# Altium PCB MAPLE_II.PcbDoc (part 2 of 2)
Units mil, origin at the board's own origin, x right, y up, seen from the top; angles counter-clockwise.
Board outline 3200 x 2150 mil, 6 copper layers (Top Side, Ground Plane, MidLayer1, MidLayer2, Power Plane, Bottom Side), stack 49.2 mil thick; 130 components, 162 nets, 713 pads, 399 vias.
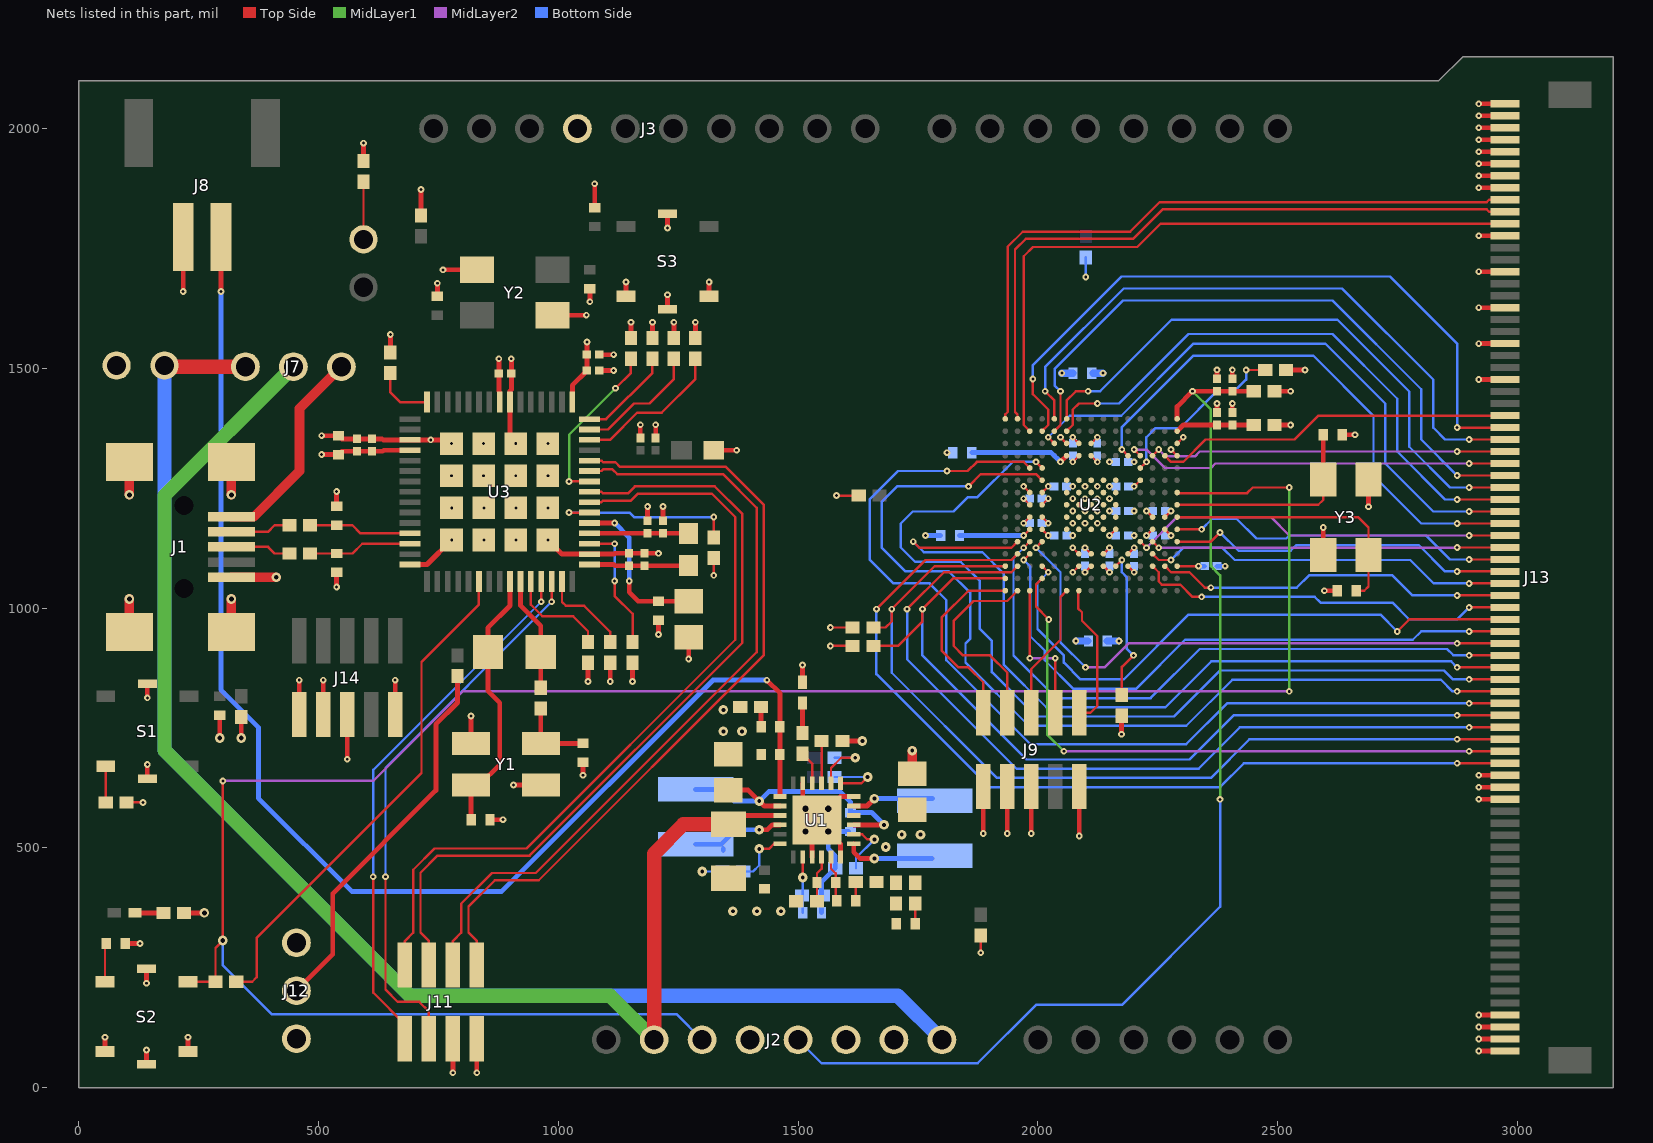
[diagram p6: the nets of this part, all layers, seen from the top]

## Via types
v1: diameter 14, hole 6, Top Side to Bottom Side, 362 vias
v2: diameter 20, hole 8, Top Side to Bottom Side, 23 vias
v3: diameter 20, hole 10, Top Side to Bottom Side, 10 vias
v4: diameter 25.98, hole 12.99, Top Side to Bottom Side, tented top, 4 vias

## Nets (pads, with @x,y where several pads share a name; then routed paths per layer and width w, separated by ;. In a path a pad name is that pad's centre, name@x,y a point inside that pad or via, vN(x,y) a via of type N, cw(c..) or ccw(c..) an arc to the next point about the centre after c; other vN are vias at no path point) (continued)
GND: C1.1 C2.1 C3.1 C4.1 C5.1 C6.1 C7.1 C8.1 C10.1 C14.1 C15.1 C16.1 C17.1 C18.1 C19.1 C20.1 C21.1 C22.1 C23.1 C24.1 C25.1 C26.1 C27.1 C28.1 C29.1 C30.1 C31.1 C32.1 C33.1 C34.1 C35.1 C36.1 C37.1 C38.1 C39.1 C40.1 C41.1 C43.1 C44.1 C47.1 C48.1 C49.1 C50.1 C51.1 C52.1 C53.1 C54.1 C55.1 C56.1 C57.1 C58.1 C59.1 C60.1 C61.1 C62.1 C63.1 J1.5 J1.S J2.2 J2.3 J3.7 J6.1 J8.2 J9.3 J9.5 J9.9 J11.4 J12.3 J13.1 J13.2 J13.3 J13.4 J13.11 J13.16 J13.17 J13.22 J13.23 J13.57 J13.58 J13.60 J13.78 J13.80 J14.3 J14.5 J14.9 R2.2 R4.2 R5.2 R6.2 R10.2 R12.1 R18.2 R20.2 R24.2 R33.2 R39.2 S1.5 S1.6 S2.3 S2.4 S2.5 S2.6 S3.3 S3.4 S3.5 S3.6 U1.3 U1.6 U1.12 U1.17 U1.25 U2.D5 U2.D7 U2.D8 U2.D9 U2.F2 U2.F6 U2.F7 U2.F8 U2.F9 U2.F10 U2.F12 U2.G2 U2.G6 U2.G7 U2.G8 U2.G9 U2.G10 U2.G12 U2.H6 U2.H7 U2.H8 U2.H9 U2.H10 U2.H12 U2.J6 U2.J7 U2.J8 U2.J9 U2.J10 U2.K6 U2.K7 U2.K8 U2.K9 U2.K10 U2.M1 U2.M8 U2.M9 U2.N1 U3.7 U3.18 U3.30 U3.47 U3.PAD1 U3.PAD2 U3.PAD3 U3.PAD4 U3.PAD5 U3.PAD6 U3.PAD7 U3.PAD8 U3.PAD9 U3.PAD10 U3.PAD11 U3.PAD12 U3.PAD13 U3.PAD14 U3.PAD15 U3.PAD16 Y1.2 Y1.4 Y2.2 Y2.4 Y3.2 Y3.4 | length 5115.7
  Top Side w5: R2.2@100,594.98 v1(134.35,594.98) ; U2.F12@2008.86,1164.37 v1(2021.65,1151.57) ; U2.G12@2008.86,1189.96 v1(2021.65,1177.17) ; U2.H12@2008.86,1215.55 v1(2021.65,1228.35) ; v1(2072.83,1125.98) U2.D9@2085.63,1113.19 ; v1(2072.83,1305.12) U2.M9@2085.63,1317.91 ; v1(2098.43,1125.98) U2.D8@2111.22,1113.19 ; U2.M8@2111.22,1317.91 v1(2124.02,1305.12) ; U2.D7@2136.81,1113.19 v1(2149.61,1125.98) ; v1(2149.61,1151.57) U2.F6@2162.4,1164.37 ; U2.D5@2187.99,1113.19 v1(2200.79,1125.98) ; U2.F2@2264.76,1164.37 v1(2277.56,1151.57) ; U2.G2@2264.76,1189.96 v1(2277.56,1202.76) ; v1(2277.56,1330.71) U2.M1@2290.35,1317.91 ; U2.N1@2290.35,1343.5 v1(2303.15,1356.3)
  Top Side w10: S2.3@55,75.49 v1(55,105.37) ; C41.1@96.95,300.69 v1(127.95,300.69) ; S2.6@141.61,48.92 v1(141.61,78.8) ; v1(141.61,217.86) S2.5@141.61,247.74 ; S1.6@143.31,644 v1(143.31,673.87) ; v1(143.31,812.94) S1.5@143.31,842.81 ; v1(218,1660.32) J8.2@218,1774 ; S2.4@228.23,75.49 v1(228.23,105.37) ; v3(294.29,729.33) C1.1@294.29,776.87 ; v1(506.69,1359.69) C52.1@542,1359.69 548.69,1352.99 C53.1@612,1352.99 633.01,1352.99 ; J14.3@510,778.23 v1(510,850) ; v1(538,1044) C40.1@538,1074.63 ; C39.1@538,1212.69 v1(538,1243.31) ; v1(560,685) J14.5@560,778.23 ; R20.2@594,1932.31 v1(594,1969.65) ; 635.11,1350.89 U3.18@690.94,1350.89 U3.PAD13@769.69,1350.89 ; R24.2@650,1533.31 v1(650,1570.62) ; J14.9@660,778.23 v1(660,850) ; U3.30@690.94,1091.04 726.38,1091.04 U3.PAD16@777.56,1142.22 ; C61.1@748,1650.3 v1(748,1677.36) ; v1(759.72,1705.41) Y2.2@830.42,1705.41 ; v1(780.31,31.32) J11.4@780.31,102.36 ; Y1.4@818.33,718 v1(818.33,775.17) ; C5.1@857.7,559 v1(884.77,559) ; U3.PAD5@899.61,1354.82 U3.7@899.61,1429.63 899.61,1452.61 902.26,1455.26 v1@902.26,1520 ; v1(906.83,631.39) Y1.2@964,631.39 ; U3.PAD4@978.35,1142.22 1007.87,1112.7 U3.47@1064.96,1112.7 1116.3,1112.7 1117.99,1114.39 C50.1@1147.53,1114.39 C51.1@1179.52,1114.39 v1(1209,1114.39) ; Y2.4@987.9,1610.93 v1(1058.6,1610.93) ; v1(1051.52,651.56) C4.1@1051.52,678.63 ; v1(1066,1638.98) C60.1@1066,1666.04 ; C59.1@1076,1835.11 v1(1076,1885) ; C49.1@1085.46,1495.53 v1(1115.47,1495.53) ; C48.1@1085.46,1528.53 v1(1115.47,1528.53) ; S3.3@1141.41,1650.07 v1(1141.41,1679.95) ; R33.2@1151.57,1563.48 v1(1151.57,1596.18) ; v1(1155,847) R39.2@1155,886.35 ; C58.1@1171.19,1354.98 v1(1171.19,1382.44) ; C55.1@1186.39,1181.98 v1(1186.39,1211.99) ; C57.1@1203.18,1354.98 v1(1203.18,1382.44) ; v1(1209,945) C44.1@1209,975.03 ; C56.1@1218.39,1181.99 v1(1218.37,1211.99) ; S3.6@1228.02,1623.5 v1(1228.02,1653.37) ; v1(1228.02,1792.44) S3.5@1228.02,1822.31 ; v1(1272,894) C43.1@1272,939.6 ; S3.4@1314.64,1650.07 v1(1314.64,1679.95) ; U1.25@1509.72,587.52 U1.17@1509.72,634.76 ; U1.3@1529.41,481.22 U1.25@1529.41,548.15 ; U1.25@1539.25,557.99 1588.46,508.78 U1.6@1588.46,481.22 ; U1.25@1588.46,607.2 U1.12@1616.02,607.2 ; R5.2@1592.56,722.99 v2(1634.25,722.99) ; v1(1936.29,530) J9.3@1936.29,628.3 ; v1(1986.29,530) J9.5@1986.29,628.3 ; v1(2086.29,525) J9.9@2086.29,628.3 ; C15.1@2373.52,1407.87 v1(2373.52,1426.67) ; C30.1@2373.52,1478.05 v1(2373.52,1496.85) ; C16.1@2405.51,1407.87 v1(2405.51,1426.67) ; C29.1@2405.51,1478.05 v1(2405.51,1496.85) ; R18.2@2517.56,1496.58 v1(2556.91,1496.58) ; Y3.4@2594.98,1111.22 v1(2594.98,1168.39) ; v1(2597.44,1036.42) C62.1@2624.51,1036.42 ; C63.1@2634.35,1361.58 v1(2661.42,1361.58) ; v1(2689.47,1211.53) Y3.2@2689.47,1268.7 ; v1(2919.25,101.58) J13.80@2974.25,101.58 ; v1(2919.25,151.58) J13.78@2974.25,151.58 ; v1(2919.25,601.58) J13.60@2974.25,601.58 ; v1(2919.25,626.58) J13.57@2974.25,626.58 ; v1(2919.25,651.58) J13.58@2974.25,651.58 ; v1(2919.25,1476.58) J13.23@2974.25,1476.58 ; v1(2919.25,1551.58) J13.22@2974.25,1551.58 ; v1(2919.25,1626.58) J13.17@2974.25,1626.58 ; v1(2919.25,1701.58) J13.16@2974.25,1701.58 ; v1(2919.25,1776.58) J13.11@2974.25,1776.58 ; v1(2919.25,1976.58) J13.3@2974.25,1976.58 ; v1(2919.25,2001.58) J13.4@2974.25,2001.58 ; v1(2919.25,2026.58) J13.1@2974.25,2026.58 ; v1(2919.25,2051.58) J13.2@2974.25,2051.58
  Top Side w20: J1.S@105.91,950.49 v3(105.91,1019.19) ; v3(105.91,1236.12) J1.S@105.91,1304.82 ; J1.S@318.5,950.49 v3(318.5,1019.19) ; J1.5@318.5,1064.67 v3(412.11,1064.67) ; v3(318.5,1236.12) J1.S@318.5,1304.82 ; C10.1@1738.25,654.39 v2(1738.25,702.99)
  Bottom Side w10: C6.1@1548.62,364.99 1548.62,429.01 R12.1@1577.6,457.99 1577.6,483.64 1562.87,498.37 v4(1562.87,534.37) C7.1@1605.31,534.37 ; v1(1765.75,1151.57) C17.1@1797.24,1151.57 ; C28.1@2373.72,1087.6 v1(2390.6,1087.6)
  Bottom Side w15: v1(2079.25,931.58) C19.1@2104.57,931.58 ; C31.1@2114.68,1490 v1(2136,1490)
  other v1: 778,1142 844.93,1142 911.86,1142 978.79,1142 2072.83,1177.17 2098.43,1177.17 2124.02,1177.17 2072.83,1202.76 2098.43,1202.76 2124.02,1202.76 2149.61,1202.76 778,1209 844.93,1209 911.86,1209 978.79,1209 2072.83,1228.35 2098.43,1228.35 2124.02,1228.35 2149.61,1228.35 2072.83,1253.94 2098.43,1253.94 2124.02,1253.94 2149.61,1253.94 777.56,1276.08 844.49,1276.08 911.42,1276.08 978.35,1276.08 2149.61,1305.12 1810.53,1324.31 777.56,1343.01 844.49,1343.01 911.42,1343.01 978.35,1343.01 734.25,1350.89 902,1520
  other v2: 1364.25,367.99 1414.25,367.99 1464.25,367.99 1344.25,742.99 1383.25,742.99 1344.25,787.99
  other v4: 1515.63,534.37 1515.63,581.61 1562.87,581.61
HD0: J13.28 U2.M2 | length 754.7
  Top Side w5: U2.M2@2264.76,1317.91 2277.56,1305.12 2303.15,1305.12 2349.61,1351.58 2535.14,1351.58 2585.14,1401.58 J13.28@2974.25,1401.58
HD1: J13.29 U2.M3 | length 750.4
  Top Side w5: U2.M3@2239.17,1317.91 v1(2251.97,1330.71) ; v1(2874.25,1326.58) J13.29@2974.25,1326.58
  MidLayer2 w5: v1(2251.97,1330.71) 2266.1,1316.58 2327.41,1316.58 2337.41,1326.58 v1(2874.25,1326.58)
HD2: J13.32 U2.M4 | length 811.3
  Top Side w5: v1(2200.79,1330.71) U2.M4@2213.58,1317.91 ; v1(2899.25,1301.58) J13.32@2974.25,1301.58
  MidLayer2 w5: v1(2200.79,1330.71) 2226.38,1330.71 2264.76,1292.32 2360.73,1292.32 2369.98,1301.58 v1(2899.25,1301.58)
HD3: J13.35 U2.M5 | length 1143.9
  Top Side w5: v1(2175.2,1330.71) U2.M5@2187.99,1317.91 ; v1(2874.25,1176.58) J13.35@2974.25,1176.58
  Bottom Side w5: v1(2175.2,1330.71) 2175.2,1377.52 2324.25,1526.58 2574.25,1526.58 2699.8,1401.03 2699.8,1276.03 2799.25,1176.58 v1(2874.25,1176.58)
HD4: J13.39 U2.E1 | length 735.5
  Top Side w5: U2.E1@2290.35,1138.78 2360.73,1138.78 v1(2379.92,1157.97) ; v1(2874.25,1076.58) J13.39@2974.25,1076.58
  Bottom Side w5: v1(2379.92,1157.97) 2418.31,1119.59 2527.26,1119.59 2539.25,1131.58 2794.25,1131.58 2849.25,1076.58 v1(2874.25,1076.58)
HD5: J13.40 U2.F1 | length 733.6
  Top Side w5: U2.F1@2290.35,1164.37 v1(2341.54,1164.37) ; v1(2899.25,1101.58) J13.40@2974.25,1101.58
  Bottom Side w5: v1(2341.54,1164.37) 2363.74,1186.58 2414.25,1186.58 2455.65,1145.18 2517.85,1145.18 2524.25,1151.58 2809.25,1151.58 2859.25,1101.58 v1(2899.25,1101.58)
HD6: J13.27 U2.P12 | length 1450.5
  Top Side w5: v1(1989.67,1477.85) 1989.67,1445.87 2021.65,1413.88 2021.65,1381.89 U2.P12@2008.86,1369.09 ; v1(2874.25,1376.58) J13.27@2974.25,1376.58
  Bottom Side w5: v1(1989.67,1477.85) 1989.67,1506.99 2174.25,1691.58 2734.25,1691.58 2874.25,1551.58 v1(2874.25,1376.58)
HD7: J13.53 R28.2 U2.C15 | length 1878.7
  Top Side w5: R28.2@1656.99,959.65 1682.58,959.65 1695.37,972.44 v1(1695.37,998.03) 1784.94,1087.6 U2.C15@1932.09,1087.6 ; v1(2874.25,726.58) J13.53@2974.25,726.58
  Bottom Side w5: v1(1695.37,998.03) 1695.37,865.46 1914.67,646.16 2360.73,646.16 2441.15,726.58 v1(2874.25,726.58)
HD8: J13.51 R31.2 U2.B15 | length 1787.8
  Top Side w5: R31.2@1656.99,921.26 1708.17,921.26 1759.35,972.44 v1(1759.35,998.03) 1823.33,1062.01 U2.B15@1932.09,1062.01 ; v1(2874.25,776.58) J13.51@2974.25,776.58
  Bottom Side w5: v1(1759.35,998.03) 1759.35,901.48 1976.28,684.55 2315.94,684.55 2407.98,776.58 v1(2874.25,776.58)
HD9: J13.56 U2.B12 | length 1312.8
  Top Side w5: U2.B12@2008.86,1062.01 1996.06,1049.21 1996.06,1003.31 v1(2022.79,976.58) ; v1(2899.25,701.58) J13.56@2974.25,701.58
  MidLayer2 w5: v1(2054.25,701.58) v1(2899.25,701.58)
  MidLayer1 w5: v1(2022.79,976.58) 2019.25,973.04 2019.25,736.58 v1(2054.25,701.58)
HD10: J13.43 U2.C12 | length 1253.6
  Top Side w5: U2.C12@2008.86,1087.6 v1(2021.65,1074.8) ; v1(2749.25,951.58) 2774.25,976.58 J13.43@2974.25,976.58
  Bottom Side w5: v1(2021.65,1074.8) 1999.25,1052.4 1999.25,956.58 2054.25,901.58 2054.25,886.58 2089.25,851.58 2179.25,851.58 2314.25,986.58 2714.25,986.58 v1(2749.25,951.58)
HD11: J13.33 U2.P10 | length 1224.2
  Top Side w5: U2.P10@2060.04,1369.09 2072.83,1381.89 2072.83,1413.88 2085.63,1426.67 v1(2124.02,1426.67) ; v1(2874.25,1226.58) J13.33@2974.25,1226.58
  Bottom Side w5: v1(2124.02,1426.67) 2169.35,1426.67 2314.25,1571.58 2614.25,1571.58 2749.25,1436.58 2749.25,1326.58 2849.25,1226.58 v1(2874.25,1226.58)
HD12: J13.34 U2.R10 | length 1234.7
  Top Side w5: U2.R10@2060.04,1394.69 2060.04,1433.07 2079.23,1452.26 v1(2104.82,1452.26) ; v1(2899.25,1251.58) J13.34@2974.25,1251.58
  Bottom Side w5: v1(2104.82,1452.26) 2129.94,1452.26 2279.25,1601.58 2624.25,1601.58 2774.25,1451.58 2774.25,1336.58 2859.25,1251.58 v1(2899.25,1251.58)
HD13: J13.36 U2.N11 | length 1269.8
  Top Side w5: v1(2021.65,1356.3) U2.N11@2034.45,1343.5 ; v1(2899.25,1201.58) J13.36@2974.25,1201.58
  Bottom Side w5: v1(2021.65,1356.3) 2066.44,1401.08 2173.76,1401.08 2324.25,1551.58 2599.25,1551.58 2724.25,1426.58 2724.25,1301.58 2824.25,1201.58 v1(2899.25,1201.58)
HD14: J13.31 U2.P11 | length 1351.3
  Top Side w5: U2.P11@2034.45,1369.09 2047.24,1381.89 v1(2047.24,1452.26) ; v1(2874.25,1276.58) J13.31@2974.25,1276.58
  Bottom Side w5: v1(2047.24,1452.26) 2035,1464.51 2035,1499 2177.58,1641.58 2614.25,1641.58 2799.25,1456.58 2799.25,1351.58 v1(2874.25,1276.58)
HD15: J13.30 U2.R11 | length 1331.8
  Top Side w5: v1(2015.26,1452.26) 2034.45,1433.07 U2.R11@2034.45,1394.69 ; v1(2899.25,1351.58) J13.30@2974.25,1351.58
  Bottom Side w5: v1(2015.26,1452.26) 2015.26,1502.58 2179.25,1666.58 2634.25,1666.58 2824.25,1476.58 2824.25,1376.58 2849.25,1351.58 v1(2899.25,1351.58)
HD16: J13.52 U2.L13 | length 2089.8
  Top Side w5: v1(1810.53,1285.93) 1853.6,1285.93 1872.79,1305.12 1970.47,1305.12 U2.L13@1983.27,1292.32 ; v1(2899.25,801.58) J13.52@2974.25,801.58
  Bottom Side w5: v1(1810.53,1285.93) 1708.6,1285.93 1649.25,1226.58 1649.25,1101.58 1699.25,1051.58 1774.25,1051.58 1809.25,1016.58 1809.25,891.58 1984.3,716.54 2309.55,716.54 2394.59,801.58 v1(2899.25,801.58)
HD17: J13.50 U2.L12 | length 1953.2
  Top Side w5: v1(1996.06,1305.12) U2.L12@2008.86,1292.32 ; v1(2899.25,851.58) J13.50@2974.25,851.58
  Bottom Side w5: v1(1996.06,1305.12) 1947.79,1305.12 1874.25,1231.58 1854.25,1231.58 1824.25,1201.58 1739.25,1201.58 1714.25,1176.58 1714.25,1126.58 1744.25,1096.58 1839.25,1096.58 1879.25,1056.58 1879.25,956.58 1904.25,931.58 1904.25,866.58 1996.72,774.11 2283.96,774.11 2379.92,870.08 2846.95,870.08 2865.45,851.58 v1(2899.25,851.58)
HD18: J13.49 U2.K12 | length 2061.8
  Top Side w5: v1(1855.32,1253.94) 1880.91,1279.53 1996.06,1279.53 U2.K12@2008.86,1266.73 ; v1(2874.25,826.58) J13.49@2974.25,826.58
  Bottom Side w5: v1(1855.32,1253.94) 1706.61,1253.94 1674.25,1221.58 1674.25,1126.58 1724.25,1076.58 1814.25,1076.58 1859.25,1031.58 1859.25,936.58 1849.25,926.58 1849.25,886.58 1980.91,754.92 2309.55,754.92 2405.51,850.89 2840.55,850.89 2864.86,826.58 v1(2874.25,826.58)
HD19: J13.45 U2.E12 | length 1206.2
  Top Side w5: v1(1996.06,1125.98) U2.E12@2008.86,1138.78 ; v1(2874.25,926.58) J13.45@2974.25,926.58
  MidLayer2 w5: v1(2099.25,876.58) 2139.25,876.58 2189.25,926.58 v1(2874.25,926.58)
  Bottom Side w5: v1(1996.06,1125.98) 2047.24,1074.8 2047.24,928.59 2098.79,877.04 v1@2098.79,876.11
HD20: J13.48 U2.E13 | length 1361.1
  Top Side w5: v1(1970.47,1125.98) U2.E13@1983.27,1138.78 ; v1(2899.25,901.58) J13.48@2974.25,901.58
  Bottom Side w5: v1(1970.47,1125.98) 1949.25,1104.76 1949.25,901.58 2038.33,812.5 2235.17,812.5 2337.54,914.86 2853.35,914.86 2866.14,902.07 2898.76,902.07 v1(2899.25,901.58)
HD21: J13.46 U2.D13 | length 1279.5
  Top Side w5: v1(1970.47,1100.39) U2.D13@1983.27,1113.19 ; v1(2899.25,951.58) J13.46@2974.25,951.58
  Bottom Side w5: v1(1970.47,1100.39) 1984.25,1086.61 1984.25,941.58 2014.25,911.58 2014.25,891.58 2074.14,831.69 2204.37,831.69 2306.73,934.06 2781.73,934.06 2799.25,951.58 v1(2899.25,951.58)
HD22: J13.44 U2.C3 | length 802.7
  Top Side w5: U2.C3@2239.17,1087.6 2251.97,1074.8 2251.97,1055.61 2258.37,1049.21 2296.75,1049.21 2322.34,1023.62 v1(2341.54,1023.62) ; v1(2899.25,1001.58) J13.44@2974.25,1001.58
  Bottom Side w5: v1(2341.54,1023.62) 2577.21,1023.62 2589.25,1011.58 2739.25,1011.58 2774.25,976.58 2874.25,976.58 v1(2899.25,1001.58)
HD23: J13.41 U2.C2 | length 755.8
  Top Side w5: U2.C2@2264.76,1087.6 2277.56,1074.8 2316.03,1074.8 2348.02,1042.81 v1(2360.73,1042.81) ; v1(2874.25,1026.58) J13.41@2974.25,1026.58
  Bottom Side w5: v1@2360.98,1042.56 2539.61,1042.56 2565.45,1068.41 2739.25,1068.41 2781.08,1026.58 v1(2874.25,1026.58)
HD24: J13.47 U2.E14 | length 1761.6
  Top Side w5: v1(1740.16,1138.78) 1752.95,1125.98 1944.88,1125.98 U2.E14@1957.68,1138.78 ; v1(2874.25,876.58) J13.47@2974.25,876.58
  Bottom Side w5: v1(1740.16,1138.78) 1762.36,1116.58 1884.25,1116.58 1929.25,1071.58 1929.25,881.58 2017.52,793.31 2265.98,793.31 2361.94,889.27 2861.56,889.27 v1(2874.25,876.58)
HD25: J13.55 U2.D14 | length 1906.5
  Top Side w5: v1(1663.39,998.03) 1765.75,1100.39 1944.88,1100.39 U2.D14@1957.68,1113.19 ; v1(2874.25,676.58) J13.55@2974.25,676.58
  Bottom Side w5: v1(1663.39,998.03) 1663.39,862.44 1898.86,626.97 2379.92,626.97 2429.53,676.58 v1(2874.25,676.58)
HD26: J13.54 U2.C14 | length 1749.1
  Top Side w5: v1(1727.36,998.03) 1804.13,1074.8 1944.88,1074.8 U2.C14@1957.68,1087.6 ; v1(2899.25,751.58) J13.54@2974.25,751.58
  Bottom Side w5: v1(1727.36,998.03) 1727.36,893.47 1955.48,665.35 2335.14,665.35 2421.36,751.58 v1(2899.25,751.58)
HD27: J13.42 U2.D3 | length 782.3
  Top Side w5: U2.D3@2239.17,1113.19 2251.97,1100.39 v1(2277.56,1100.39) ; v1(2899.25,1051.58) J13.42@2974.25,1051.58
  Bottom Side w5: v1(2277.56,1100.39) 2303.74,1126.58 2384.25,1126.58 2410.44,1100.39 2776.57,1100.39 2825.39,1051.58 v1(2899.25,1051.58)
HD28: J13.37 U2.E3 | length 740.4
  Top Side w5: U2.E3@2239.17,1138.78 v1(2251.97,1125.98) ; v1(2874.25,1126.58) J13.37@2974.25,1126.58
  MidLayer2 w5: v1(2251.97,1125.98) v1@2874.25,1125.98
HD29: J13.38 U2.E4 | length 808.4
  Top Side w5: U2.E4@2213.58,1138.78 v1(2226.38,1125.98) ; v1(2899.25,1151.58) J13.38@2974.25,1151.58
  MidLayer2 w5: v1(2226.38,1125.98) 2290.35,1189.96 2485.87,1189.96 2524.25,1151.58 v1(2899.25,1151.58)
JTAG_TCK: J9.4 U2.A14 | length 430.5
  Top Side w5: J9.4@1936.29,781.84 1936.29,865.87 1900.59,901.58 1844.25,901.58 1824.25,921.58 1824.25,973.37 1865.92,1015.03 1936.29,1015.03 U2.A14@1957.68,1036.42
JTAG_TDI: J9.8 U2.A13 | length 307.6
  Top Side w5: v1(1983.27,895.67) U2.A13@1983.27,1036.42 ; J9.8@2036.29,781.84 v1(2036.29,895.67)
  MidLayer2 w5: v1(1983.27,895.67) v1(2036.29,895.67)
JTAG_TDO: J9.6 U2.A10 | length 285.1
  Top Side w5: J9.6@1986.29,781.84 1986.29,873.1 2047.24,934.06 2047.24,1023.62 U2.A10@2060.04,1036.42
JTAG_TMS: J9.2 U2.A15 | length 402.9
  Top Side w5: J9.2@1886.29,781.84 1886.29,845.5 1855.21,876.58 1834.25,876.58 1799.25,911.58 1799.25,980.35 1855.31,1036.42 U2.A15@1932.09,1036.42
JTAG_TRST: J9.10 U2.A9 | length 301.9
  Top Side w5: J9.10@2085.63,781.84 2109.52,781.84 2124.25,796.58 2124.25,941.58 2092.03,973.8 2092.03,991.63 2084,999.66 2084,1034.79 U2.A9@2085.63,1036.42
LINK_LED: J11.6 U3.43 | length 1160.5
  Top Side w5: v1(639.76,440) 639.76,204.72 665.35,179.13 710.14,179.13 730.31,158.96 J11.6@730.31,102.36 ; v1(986.22,1013.29) U3.43@986.22,1055.61
  Bottom Side w5: v1(639.76,440) 639.76,666.83 v1(986.22,1013.29)
M\C\U\_\R\S\T\: J2.6 R22.1 S2.1 U2.J1 | length 4562.7
  Top Side w5: S2.1@228.23,221.16 R22.1@285.35,221.16 285.35,291.74 v3(300.69,307.09) v1(300.69,639.76) ; U2.J1@2290.35,1241.14 2291.5,1240 2436.36,1240 2447.94,1251.58 v1(2524.25,1251.58)
  MidLayer2 w5: v1(300.69,639.76) 614.17,639.76 800.99,826.58 v1(2524.25,826.58)
  MidLayer1 w5: v1(2524.25,826.58) v1(2524.25,1251.58)
  Bottom Side w5: v3(300.69,307.09) 300.69,255.14 402.29,153.54 1246.46,153.54 J2.6@1300,100
NetC4_2: C4.2 R25.2 Y1.3 | length 159.9
  Top Side w10: Y1.3@963.58,718.42 R25.2@963.58,790.85 ; Y1.3@964,718 C4.2@1051.52,718
NetC5_2: C5.2 R21.1 U3.39 Y1.1 | length 543.6
  Top Side w10: C5.2@818.33,559 Y1.1@818.33,631.39 ; Y1.1@835.39,631.39 878,674 878,803 853.35,827.65 R21.1@853.35,908.46 853.35,959.35 899.61,1005.61 U3.39@899.61,1055.61
NetC6_2: C6.2 R4.1 U1.2 | length 116.2
  Top Side w5: v2(1509.72,438.46) U1.2@1509.72,481.22
  Bottom Side w5: C6.2@1509.72,364.99 v2(1509.72,438.46)
NetC8_2: C8.2 C9.2 J8.1 U1.19 | length 2779.8
  Top Side w10: v1(296.74,1660.32) J8.1@296.74,1774 ; v1(1435,850) 1462.48,822.52 U1.19@1462.48,607.2
  Bottom Side w10: v1(296.74,1660.32) 296.74,830 375,751.74 375,603.84 569.39,409.45 882.12,409.45 1322.67,850 v1(1435,850)
NetC9_1: C9.1 R6.1 | length 41
  Top Side w10: C9.1@1422.88,752.99 R6.1@1422.91,793.99
NetC11_1: C11.1 C13.1 R7.2 R9.2 R10.1 U1.4 | length 96.2
  Top Side w5: R10.1@1539.57,388.99 1539.57,447.3 1549.09,456.83 U1.4@1549.09,481.22
NetC11_2: C11.2 R8.2 | length 42
  Top Side w5: C11.2@1744.25,342.3 R8.2@1744.25,384.33
NetC12_1: C12.1 R9.1 | length 38.7
  Top Side w5: C12.1@1619.94,389.99 R9.1@1619.94,428.67
NetC12_2: C12.2 C13.2 U1.5 | length 95.2
  Top Side w5: U1.5@1568.78,481.22 1568.78,456.83 1578.31,447.3 C12.2@1578.31,389.99
NetC15_2: C15.2 C16.2 R16.2 U2.P1 | length 165.2
  Top Side w10: U2.P1@2290.35,1369.09 2303.15,1381.89 C15.2@2373.52,1381.89 C16.2@2405.51,1381.89 R16.2@2450.3,1381.89
NetC17_2: C17.2 U2.F13 | length 152
  Top Side w5: v1(1970.47,1151.57) U2.F13@1983.27,1164.37
  Bottom Side w10: C17.2@1836.61,1151.57 v1(1970.47,1151.57)
NetC18_2: C18.2 U2.M10 | length 211.1
  Top Side w10: v1(2047.24,1305.12) U2.M10@2060.04,1317.91
  Bottom Side w10: C18.2@1862.2,1324.31 2028.05,1324.31 v1(2047.24,1305.12)
NetC41_2: C41.2 S2.2 | length 76.9
  Top Side w5: S2.2@55,221.16 C41.2@55,298.11
NetC43_2: C43.2 C44.2 U3.50 | length 341.6
  Top Side w10: U3.50@1064.96,1177.66 v1(1117.65,1177.66) ; v1(1148,1056.65) 1148,1033 1166.6,1014.4 C44.2@1209,1014.4 C43.2@1272,1014.4
  Bottom Side w10: v1(1117.65,1177.66) 1148,1147.31 v1(1148,1056.65)
NetJ10_2: J10.2 R20.1 | length 120
  Top Side w5: J10.2@594,1769 R20.1@594,1889
NetJ12_2: J12.2 R43.1 | length 795.1
  Top Side w10: J12.2@454.23,202.36 530,278.13 530,405 745,620 745,758 790,803 R43.1@790,858.35
NetL1_1: L1.1 U1.22 | length 196.9
  Top Side w10: v2(1419.25,537.99) 1436.25,537.99 1446.41,548.15 U1.22@1462.48,548.15
  Bottom Side w10: L1.1@1286.25,507.9 1340.17,507.9 1370.25,537.99 v2(1419.25,537.99) ; L1.1@1344.17,494.9 L1.1@1344.17,498.9
NetL2_1: L2.1 U1.7 | length 186.4
  Top Side w10: U1.7@1616.02,508.78 1616.02,491.22 1629.25,477.99 v2(1659.25,477.99)
  Bottom Side w10: v2(1659.25,477.99) L2.1@1779.34,477.99
NetL2_2: L2.2 U1.11 | length 170.7
  Top Side w10: U1.11@1616.02,587.52 1643.78,587.52 v2(1659.25,602.99)
  Bottom Side w10: v2(1659.25,602.99) L2.2@1780.34,602.99
NetLED1_1: LED1.1 R3.2 | length 59.1
  Top Side w10: LED1.1@117.62,364.67 R3.2@176.67,364.67
NetLED2_2: LED2.2 R11.1 | length 62.7
  Top Side w10: R11.1@1509.25,739.64 LED2.2@1509.25,802.33
NetR2_1: R2.1 S1.3 | length 75.6
  Top Side w5: R2.1@56.69,594.98 S1.3@56.69,670.57
NetR5_1: R5.1 U1.15 | length 88.1
  Top Side w5: U1.15@1549.09,634.76 R5.1@1549.09,722.83
NetR11_2: R11.2 U1.16 | length 69.9
  Top Side w5: R11.2@1509.25,696.33 1529.41,676.18 U1.16@1529.41,634.76
NetR12_2: R12.2 U1.8 | length 123.4
  Top Side w5: U1.8@1616.02,528.46 1633.78,528.46 1644.25,517.99 v2(1659.25,517.99)
  Bottom Side w5: R12.2@1620.91,457.99 1620.91,479.64 v2(1659.25,517.99)
NetR13_2: R13.2 U1.13 | length 130.8
  Top Side w5: U1.13@1588.46,634.76 1631.76,634.76 v2(1645,648)
  Bottom Side w5: R13.2@1576.25,647.99 v2(1645,648)
NetR14_2: R14.2 U1.14 | length 134.1
  Top Side w5: U1.14@1568.78,634.76 1568.78,666.52 1590.25,687.99 v2(1619.25,687.99)
  Bottom Side w5: R14.2@1576.25,687.99 v2(1619.25,687.99)
NetR17_1: R17.1 U2.C6 | length 319.5
  Top Side w5: U2.C6@2162.4,1087.6 v1(2175.2,1100.39) ; R17.1@2175.2,818.9 2175.2,877.52 v1(2199.25,901.58)
  Bottom Side w5: v1(2175.2,1100.39) 2175.2,1074.8 2185,1065 2185,915.83 v1(2199.25,901.58)
NetR18_1: R18.1 U2.L4 | length 387
  Top Side w5: U2.L4@2213.58,1292.32 v1(2226.38,1305.12) ; v1(2434.25,1496.58) R18.1@2474.25,1496.58
  Bottom Side w5: v1(2226.38,1305.12) 2226.38,1356.3 2245.57,1375.49 2296.75,1375.49 2372.84,1451.58 2409.25,1451.58 2434.25,1476.58 v1(2434.25,1496.58)
NetR21_2: R21.2 R25.1 U3.40 | length 239
  Top Side w10: U3.40@921.26,1055.61 921.26,1005.74 963.58,963.42 R25.1@963.58,834.15
NetR22_2: R22.2 U3.36 | length 1063.5
  Top Side w5: R22.2@328.65,221.16 361.91,221.16 371.06,230.31 371.06,312.06 715,656 715,888 834.65,1007.65 U3.36@834.65,1055.61
NetR23_1: R23.1 U1.24 | length 120.4
  Top Side w5: v2(1419.25,497.99) 1439.25,497.99 1450.04,508.78 U1.24@1462.48,508.78
  Bottom Side w5: R23.1@1385.91,450.99 1406.25,450.99 1419.25,463.99 v2(1419.25,497.99)
NetR24_1: R24.1 U3.15 | length 124.8
  Top Side w5: R24.1@650,1490 650,1450 670.37,1429.63 U3.15@726.38,1429.63
NetR29_1: R29.1 U3.44 | length 189.9
  Top Side w5: U3.44@1007.87,1055.61 1007.87,1013.13 1016,1005 1054,1005 1108.5,950.5 R29.1@1108.5,929.65
NetR30_1: R30.1 U3.58 | length 315.9
  Top Side w5: U3.58@1064.96,1350.89 1107.78,1350.89 1164.37,1407.48 1215.55,1407.48 1285.93,1477.85 R30.1@1285.93,1520.18
NetR32_1: R32.1 U3.51 | length 390.2
  Top Side w5: v1(1022.64,1199.31) U3.51@1064.96,1199.31 ; R32.1@1324.31,1147.64 v1(1324.31,1189.96)
  Bottom Side w5: v1(1022.64,1199.31) 1148.62,1199.31 1157.97,1189.96 v1(1324.31,1189.96)
NetR33_1: R33.1 U3.54 | length 351.6
  Top Side w5: v1(1022.64,1264.27) U3.54@1064.96,1264.27 ; v1(1119.59,1458.66) 1151.57,1490.65 R33.1@1151.57,1520.18
  MidLayer1 w5: v1(1022.64,1264.27) 1022.64,1361.71 v1(1119.59,1458.66)
NetR39_1: R39.1 U3.48 | length 272.4
  Top Side w5: U3.48@1064.96,1134.35 v1(1117.65,1134.35) ; v1(1117.65,1056.65) 1117.65,1025.56 1155,988.21 R39.1@1155,930.12
  Bottom Side w5: v1(1117.65,1056.65) v1(1117.65,1134.35)
NetR40_2: R40.2 U3.41 | length 212.8
  Top Side w5: U3.41@942.91,1055.61 942.91,1007.09 967,983 1031,983 1062.01,951.99 R40.2@1062.01,929.65
NetR41_2: R41.2 U3.60 | length 200.9
  Top Side w5: U3.60@1064.96,1394.19 1099.9,1394.19 1196.36,1490.65 R41.2@1196.36,1520.18
NetR42_2: R42.2 U3.59 | length 262.1
  Top Side w5: U3.59@1064.96,1372.54 1103.84,1372.54 1157.97,1426.67 1189.96,1426.67 1241.14,1477.85 R42.2@1241.14,1520.18
RXI_N: J11.1 U3.56 | length 1677.7
  Top Side w5: J11.1@830.31,255.91 830.31,306 812.81,323.5 812.81,377.78 867.87,432.83 959.46,432.83 1428.88,902.25 1428.88,1215.37 1349.72,1294.53 1129.13,1294.53 1119.4,1304.25 1093.33,1304.25 1090,1307.58 U3.56@1064.96,1307.58
RXI_P: J11.3 U3.55 | length 1652.8
  Top Side w5: J11.3@780.31,255.91 780.31,306 797.81,323.5 797.81,383.99 861.66,447.83 953.25,447.83 1413.88,908.46 1413.88,1209.15 1343.5,1279.53 1122.91,1279.53 1113.19,1289.25 1093.33,1289.25 1090,1285.93 U3.55@1064.96,1285.93
SPEED_LED: J11.8 U3.42 | length 1125.8
  Top Side w5: v1(614.17,440) 614.17,198.33 680.31,132.19 J11.8@680.31,102.36 ; v1(964.57,1013.29) U3.42@964.57,1055.61
  Bottom Side w5: v1(614.17,440) 614.17,662.89 v1(964.57,1013.29)
TXO_N: J11.5 U3.53 | length 1688.4
  Top Side w5: J11.5@730.31,255.91 730.31,306 712.81,323.5 712.81,448.31 748.52,484.02 940.27,484.02 1384.09,927.84 1384.09,1196.17 1326.33,1253.94 1159.82,1253.94 1145.18,1239.29 1093.33,1239.29 1090,1242.62 U3.53@1064.96,1242.62
TXO_P: J11.7 U3.52 | length 1663.5
  Top Side w5: J11.7@680.31,255.91 680.31,306 697.81,323.5 697.81,454.52 742.31,499.02 934.06,499.02 1369.09,934.06 1369.09,1189.96 1320.12,1238.94 1166.04,1238.94 1151.39,1224.29 1093.33,1224.29 1090,1220.96 U3.52@1064.96,1220.96
USB_COMM_N: C39.2 R27.2 U3.27 | length 215.3
  Top Side w5: R27.2@482.65,1173 556.59,1173 571,1173 588,1156 U3.27@690.94,1156
USB_COMM_P: C40.2 R26.2 U3.28 | length 216.7
  Top Side w5: R26.2@482.65,1114 556.59,1114 571,1114 591.35,1134.35 U3.28@690.94,1134.35
USB_EXT_N: J1.2 R27.1 | length 126.6
  Top Side w5: J1.2@318.5,1159.15 394.89,1159.15 408.73,1173 R27.1@439.35,1173
USB_EXT_P: J1.3 R26.1 | length 126.5
  Top Side w5: J1.3@318.5,1127.66 394.98,1127.66 408.64,1114 R26.1@439.35,1114
USB_N: J13.9 U2.R14 | length 1413.9
  Top Side w5: U2.R14@1957.68,1394.69 1957.68,1404 1952.38,1409.3 1952.38,1747.66 1974.67,1769.94 2198.58,1769.94 2260.22,1831.58 2936,1831.58 2941,1826.58 J13.9@2974.25,1826.58
USB_P: J13.10 U2.R15 | length 1438.7
  Top Side w5: U2.R15@1932.09,1394.69 1932.09,1404 1937.38,1409.3 1937.38,1753.87 1968.45,1784.94 2192.37,1784.94 2254.01,1846.58 2936,1846.58 2941,1851.58 J13.10@2974.25,1851.58
USB_VBUS: J13.12 U2.P13 | length 1401.8
  Top Side w5: U2.P13@1983.27,1369.09 1970.47,1381.89 1970.47,1733.76 1989.67,1752.95 2207.19,1752.95 2255.81,1801.58 J13.12@2974.25,1801.58
V1P8: C50.2 C51.2 FB2.1 U3.46 | length 202
  Top Side w10: U3.46@1064.96,1091.04 1115.96,1091.04 1118.6,1088.4 C50.2@1147.53,1088.4 C51.2@1179.52,1088.4 FB2.1@1265.87,1088.4
V3P3: C10.2 C19.2 C20.2 C21.2 C22.2 C23.2 C24.2 C25.2 C26.2 C27.2 C31.2 C32.2 C33.2 C34.2 C35.2 C36.2 C37.2 C38.2 C47.2 C48.2 C49.2 C52.2 C53.2 C54.2 FB1.1 J2.5 J9.1 J11.2 J12.1 J13.5 J13.6 J13.7 J13.8 J13.77 J13.79 J14.1 L3.2 LED2.1 R1.1 R3.1 R7.1 R8.1 R15.1 R16.1 R17.2 R19.2 R23.2 R28.1 R29.2 R30.2 R31.1 R32.2 R34.1 R35.1 R40.1 R41.1 R42.1 U1.10 U2.C5 U2.C7 U2.C8 U2.C9 U2.F3 U2.G3 U2.G13 U2.H13 U2.J12 U2.J13 U2.K4 U2.N8 U2.N9 U2.N10 U3.1 U3.8 U3.19 | length 2090.9
  Top Side w5: v1(1324.31,1068.41) R32.2@1324.31,1104.33 ; v1(1567.42,921.26) R31.1@1613.68,921.26 ; v1(1567.42,959.65) R28.1@1613.68,959.65 ; v1(1580.22,1234.74) R15.1@1626.48,1234.74 ; v1(1880.91,281.5) R35.1@1880.91,317.42 ; v1(1970.47,1177.17) U2.G13@1983.27,1189.96 ; v1(1970.47,1228.35) U2.H13@1983.27,1215.55 ; v1(1970.47,1253.94) U2.J13@1983.27,1241.14 ; U2.J12@2008.86,1241.14 v1(2021.65,1253.94) ; v1(2047.24,1356.3) U2.N10@2060.04,1343.5 ; v1(2072.83,1074.8) U2.C9@2085.63,1087.6 ; v1(2072.83,1356.3) U2.N9@2085.63,1343.5 ; v1(2098.43,1074.8) U2.C8@2111.22,1087.6 ; U2.N8@2111.22,1343.5 v1(2124.02,1356.3) ; U2.C7@2136.81,1087.6 v1(2149.61,1074.8) ; U2.C5@2187.99,1087.6 v1(2200.79,1074.8) ; v1(2200.79,1253.94) U2.K4@2213.58,1266.73 ; v1(2226.38,1151.57) U2.F3@2239.17,1164.37 ; v1(2226.38,1202.76) U2.G3@2239.17,1189.96
  Top Side w10: R3.1@219.98,364.67 v3(262.3,364.67) ; v3(339.07,729.33) R1.1@339.07,772.93 ; J14.1@460,778.23 v1(460,850) ; v1(506.69,1320.31) C52.2@542,1320.31 548.69,1327.01 C54.2@580,1327.01 C53.2@612,1327.01 634.01,1327.01 636.23,1329.23 U3.19@690.94,1329.23 ; R19.2@714,1818.65 v1(714,1873) ; v1(830.31,31.32) J11.2@830.31,102.36 ; v1(876.28,1520) 876.28,1452.72 877.95,1451.05 U3.8@877.95,1429.63 ; U3.1@1029.53,1429.63 1029.53,1464.53 1060,1495 v1(1060,1555) ; v1(1062.01,847) R40.1@1062.01,886.35 ; v1(1108.5,847) R29.2@1108.5,886.35 ; R41.1@1196.36,1563.48 v1(1196.36,1596.18) ; R42.1@1241.14,1563.48 v1(1241.14,1596.18) ; R30.2@1285.93,1563.48 v1(1285.93,1596.18) ; FB1.1@1324.12,1329.23 v1(1371.96,1329.23) ; LED2.1@1509.25,845.64 v1(1509.25,881.58) ; v1(1886.29,530) J9.1@1886.29,628.3 ; v1(2174.25,737.23) R17.2@2174.25,776.58 ; R16.1@2493.6,1381.89 v1(2527.07,1381.89) ; L3.2@2493.6,1452.26 v1(2527.07,1452.26) ; v1(2919.25,76.58) J13.79@2974.25,76.58 ; v1(2919.25,126.58) J13.77@2974.25,126.58 ; v1(2919.25,1876.58) J13.7@2974.25,1876.58 ; v1(2919.25,1901.58) J13.8@2974.25,1901.58 ; v1(2919.25,1926.58) J13.5@2974.25,1926.58 ; v1(2919.25,1951.58) J13.6@2974.25,1951.58
  Bottom Side w5: v2(1300.25,450.99) R23.2@1342.6,450.99 ; v1(2100,1690.55) R34.1@2100,1731.3
  Bottom Side w15: v1(2050,1490) C31.2@2073.32,1490 ; C19.2@2143.94,931.58 v1(2169.25,931.58)
  other v1: 2072.83,1151.57 2200.79,1151.57 2200.79,1202.76 2200.79,1305.12
  other v2: 1683,502 1716.25,527.99 1755.25,527.99
V5P0: C2.2 J2.7 J7.2 U1.21 | length 2840.1
  Top Side w10: C2.2@1372.99,567.83 U1.21@1462.48,567.83
  Top Side w30: J2.7@1200,100 1200,488.22 1260.87,549.09 C2.2@1355.25,549.09
  MidLayer1 w30: J7.2@447.83,1503.44 179.13,1234.74 179.13,703.74 690.94,191.93 1108.07,191.93 J2.7@1200,100
V_REG: C3.2 C7.2 L1.2 U1.9 U1.20 | length 638.5
  Top Side w10: C3.2@1354.25,620.59 1396.34,620.59 v2(1419.25,597.67) 1429.41,587.52 U1.20@1462.48,587.52 ; U1.9@1616.02,548.15 v2(1679.25,548.15)
  Bottom Side w10: L1.2@1286.25,622.07 1342.17,622.07 1366.57,597.67 v2(1419.25,597.67) 1439.57,617.99 1587.25,617.99 1609.25,595.99 1609.25,573.99 1653.41,573.99 v2(1679.25,548.15)
V_USB_5P0: J1.1 J7.3 | length 435.2
  Top Side w20: J1.1@318.5,1190.65 365.35,1190.65 460.63,1285.93 460.63,1416.24 J7.3@547.83,1503.44
VA1P8: C55.2 C56.2 FB2.2 U3.49 | length 207.1
  Top Side w10: U3.49@1064.96,1156 1271.93,1156 FB2.2@1272,1155.93
VA3P3: C29.2 C30.2 J2.4 L3.1 U2.R1 | length 2332.7
  Top Side w10: U2.R1@2290.35,1394.69 2290.35,1420.28 v1(2322.34,1452.26) L3.1@2450.3,1452.26
  MidLayer1 w5: v1(2322.34,1452.26) 2360.73,1413.88 2360.73,1087.6 2379.92,1068.41 v1(2379.92,601.38)
  Bottom Side w5: J2.4@1500,100 1548.82,51.18 1874.51,51.18 1996.06,172.74 2175.2,172.74 2379.92,377.46 v1(2379.92,601.38)
VBAT: C28.2 U2.C1 | length 57.4
  Top Side w5: U2.C1@2290.35,1087.6 v1(2335.14,1087.6)
  Bottom Side w10: v1(2335.14,1087.6) C28.2@2347.74,1087.6
VIN: J2.1 J6.2 J7.1 | length 2843
  Top Side w30: J6.2@179.13,1506 181.69,1503.44 J7.1@347.83,1503.44
  Bottom Side w30: J6.2@179.13,1506 179.13,703.74 690.94,191.93 1708.07,191.93 J2.1@1800,100
XI: C62.2 U2.G1 Y3.1 | length 560.4
  Top Side w5: U2.G1@2290.35,1189.96 2667.81,1189.96 2689.47,1168.31 Y3.1@2689.47,1111.22 2689.47,1045.28 2680.61,1036.42 C62.2@2663.88,1036.42
XO: C63.2 U2.H1 Y3.3 | length 444.6
  Top Side w5: U2.H1@2290.35,1215.55 2584.65,1215.55 2594.98,1225.89 Y3.3@2594.98,1268.7
  Top Side w10: Y3.3@2594.98,1268.7 C63.2@2594.98,1361.58
pads on no net: J1. J1.4 J2.8 J8.MNT J9.7 J13.M1 J13.M2 J14.7 S1.2 S1.4 S3.1 U1.18 U1.23 U2.A1 U2.A2 U2.A4 U2.A11 U2.B1 U2.B2 U2.B3 U2.B8 U2.B10 U2.B11 U2.C10 U2.C11 U2.D2 U2.D11 U2.F4 U2.G4 U2.H14 U2.J14 U2.J15 U2.K1 U2.K2 U2.K13 U2.K14 U2.K15 U2.L1 U2.L2 U2.L3 U2.L14 U2.L15 U2.M7 U2.M11 U2.M13 U2.M14 U2.M15 U2.N6 U2.N7 U2.N12 U2.N13 U2.N14 U2.N15 U2.P7 U2.P8 U2.P9 U2.P14 U2.P15 U2.R4 U2.R5 U2.R6 U2.R7 U2.R8 U2.R9 U3.2 U3.3 U3.9 U3.10 U3.11 U3.12 U3.13 U3.16 U3.17 U3.20 U3.21 U3.22 U3.23 U3.24 U3.37 U3.45

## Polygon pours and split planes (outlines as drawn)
GND on Ground Plane (split plane): 3179.9,20.1 20.1,20.1 20.1,2079.9 2836,2079.9 2837.86,2080.09 2839.73,2080.25 2839.82,2080.28 2839.92,2080.29 2841.71,2080.83 2843.51,2081.36 2843.59,2081.4 2843.69,2081.43 2845.34,2082.32 2847,2083.18 2847.08,2083.24 2847.17,2083.29 2848.61,2084.48 2850.07,2085.65 2895.21,2129.9 3179.9,2129.9
V3P3 on Power Plane (split plane): 3179.9,20.1 20.1,20.1 20.1,2079.9 2836,2079.9 2837.86,2080.09 2839.73,2080.25 2839.82,2080.28 2839.92,2080.29 2841.71,2080.83 2843.51,2081.36 2843.59,2081.4 2843.69,2081.43 2845.34,2082.32 2847,2083.18 2847.08,2083.24 2847.17,2083.29 2848.61,2084.48 2850.07,2085.65 2895.21,2129.9 3179.9,2129.9

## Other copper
Top Side:
  region net GND: 754.25,1366.58 1004.25,1366.58 1004.25,1116.58 754.25,1116.58
  region net V3P3: 1699.25,412.99 1699.25,447.99 1679.25,467.99 1679.25,517.99 1699.25,537.99 1699.25,557.99 1694.25,562.99 1624.25,562.99 1624.25,572.99 1769.25,572.99 1769.25,417.99 1764.25,412.99
  region net GND: 1329.25,352.99 1318.25,363.99 1318.25,425 1492.24,425 1512.25,404.99 1512.25,362.99 1502.25,352.99
  region net NetC11_1: 1654.25,420.99 1674.25,420.99 1674.25,397.99 1679.25,392.99 1693.25,392.99 1693.25,377.99 1679.25,377.99 1674.25,372.99 1674.25,352.99 1679.25,347.99 1697.25,347.99 1697.25,337.99 1544.25,337.99 1529.25,352.99 1529.25,382.99 1549.25,382.99 1549.25,367.99 1554.25,362.99 1629.25,362.99 1654.25,387.99
  region net GND: 1429.25,682.99 1324.25,682.99 1324.25,787.99 1343.25,806.99 1390.25,806.99 1394.25,802.99 1394.25,727.99 1419.25,702.99 1429.25,702.99
  region net GND: 2162.4,1164.37 2162.4,1266.73 2060.04,1266.73 2060.04,1164.37
  text "GTL - TOP LAYER" at 567.75,-1314.77 h60
MidLayer2:
  text "G2 - INNER LAYER 2" at 571,-1888 h60
MidLayer1:
  text "G1 - INNER LAYER 1" at 569,-1755 h60
Bottom Side:
  text "GBL - BOTTOM LAYER" at 567.75,-2121.85 h60
Ground Plane (plane layer: these items are gaps in the copper):
  text "GP1 - GROUND PLANE 1" at 567.75,-1511.62 h60
Power Plane (plane layer: these items are gaps in the copper):
  text "GP2 - POWER PLANE 1" at 565,-2008 h60
Multi-Layer:
  text "MULTI-LAYER HOLES" at 3535,-2864 h60

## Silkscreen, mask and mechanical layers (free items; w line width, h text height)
Top Overlay:
  text "GTO - TOP SILKSCREEN" at 567.75,-1413.19 h60
Bottom Overlay:
  text "GB0 - BOTTOM SILKSCREEN" at 567.75,-2220.28 h60
Top Paste:
  text "GTP - TOP PASTE" at 567.75,-1117.91 h60
Bottom Paste:
  text "GBP - BOTTOM PASTE" at 567.75,-2318.7 h60
Top Solder:
  text "GTS - TOP SOLDER" at 567.75,-1216.34 h60
Bottom Solder:
  text "GBS - BOTTOM SOLDER" at 567.75,-2417.13 h60
Drill Guide:
  lines w2: -5580,-760 -5280,-760 ; -5580,1740 -5280,1740 ; -5580,4240 -5280,4240 ; -2930,-3260 -2930,-2960 ; -2930,6440 -2930,6740 ; -255,-3260 -255,-2960 ; -255,6440 -255,6740 ; 2420,-3260 2420,-2960 ; 2420,6440 2420,6740 ; 4920,-2960 4920,-2510 5270,-2510 ; 5095,-3260 5095,-2960 ; 5095,6440 5095,6740 ; 5270,-2960 5270,-1810 6170,-1810 ; 5270,-2710 10120,-2710 ; 5270,-2410 10120,-2410 ; 5270,-2110 6170,-2110 ; 6170,-2960 6170,-1810 ; 7745,-3260 7745,-2960 ; 8170,-2710 8170,-2410 ; 9220,-2710 9220,-2410 ; 10120,-1810 6170,-1810 ; 10120,-760 10420,-760 ; 10120,4240 10420,4240 ; -5580,-3260 -5580,6740 10420,6740 10420,-3260 -5580,-3260 ; -5280,-2960 -5280,6440 10120,6440 10120,-2960 -5280,-2960
  text "1" at -4305,6540 h90
  text "2" at -1630,6540 h90
  text "3" at 1070,6540 h90
  text "4" at 3720,6540 h90
  text "5" at 6400,6540 h90
  text "D" at 10245,5490 h90
  text "D" at -5450,5465 h90
  text "C" at -5455,2965 h90
  text "B" at 10245,490 h90
  text "B" at -5455,465 h90
  text ".Drawn" at 5345,-1935 h90
  text ".Company" at 6231.22,-1944.37 h90
  text "A" at 10245,-2010 h90
  text "A" at -5450,-2085 h90
  text ".Engineer" at 5345,-2235 h90
  text ".Number" at 6245,-2530 h90
  text ".Print_Date" at 8280,-2530 h90
  text ".Print_Date" at 5345,-2535 h90
  text ".Revision" at 9265,-2535 h90
  text "DRILL GUIDE" at 3535,-2665 h60
  text "B" at 5030,-2765 h180
  text "1:1" at 5350,-2835 h90
  text ".Pcb_File_Name_No_Path" at 6240,-2835 h90
  text "1" at 9800.91,-2880.08 h90
  text "of" at 9645,-2885 h90
  text "Sheet" at 8945,-2890 h90
  text "1" at 9331.42,-2889.92 h90
  text "Size" at 4970,-2910 h90
  text "1" at -4305,-3160 h90
  text "2" at -1630,-3160 h90
  text "3" at 1070,-3160 h90
  text "4" at 3720,-3160 h90
  text "5" at 6395,-3160 h90
  text "6" at 9070,-3160 h90
Mechanical 1:
  text "MECHANICAL LAYERS" at 3535,-965 h60
  text "LAYER - GERBER LAYERS - DESCRIPTION" at 567.75,-1019.49 h60
  text "01 Component Outline" at 3535,-1065 h60
Mechanical 2:
  circle w6: c-2000,5200 r300
  circle w6: c-2000,5200 r200
  circle w6: c-2000,5200 r100
  circle w6: c7000,5200 r300
  circle w6: c7000,5200 r200
  circle w6: c7000,5200 r100
  circle w6: c7000,400 r300
  circle w6: c7000,400 r200
  circle w6: c7000,400 r100
  lines w6: -2500,5200 -2000,5200 ; -2000,4700 -2000,5200 ; -2000,5700 -2000,5200 ; -1500,5200 -2000,5200 ; 6500,400 7000,400 ; 6500,5200 7000,5200 ; 7000,-100 7000,400 ; 7000,900 7000,400 ; 7000,4700 7000,5200 ; 7000,5700 7000,5200 ; 7500,400 7000,400 ; 7500,5200 7000,5200 ; 0,0 0,2100 2836,2100 2886,2150 3200,2150 3200,0 0,0
  text "02 PCB BOUNDRY" at 3535,-1165 h60
Mechanical 3:
  text "03 PINOUT ID" at 3535,-1265 h60
Mechanical 4:
  text "04" at 3535,-1365 h60
Mechanical 5:
  text "05" at 3535,-1465 h60
Mechanical 6:
  lines w8: -4057,2823.25 -1837,2823.25 ; -4057,2974.75 -1837,2974.75 ; -4117,1852 ccw(c-4068,1852) -4068,1803 -1826,1803 ccw(c-1826,1852) -1777,1852 -1777,3109 ccw(c-1826,3109) -1826,3158 -4068,3158 ccw(c-4068,3109) -4117,3109 -4117,1852
  text "Layer Stack Up Detail for: MAPLE_II.PcbDoc" at -4057,3028.77 h52
  text "Layer" at -4057,2918.25 h35
  text "Name" at -4057,2848.25 h35
  text "Top Side" at -4057,2748.68 h49
  text "Ground Plane" at -4057,2607.53 h49
  text "MidLayer1" at -4057,2466.39 h49
  text "MidLayer2" at -4057,2325.24 h49
  text "Power Plane" at -4057,2184.09 h49
  text "Bottom Side" at -4057,2042.95 h49
  text "Fabrication Notes" at -4000,1000 h60
  text "1. Overall board height: 50mils" at -3999.18,889.96 h60
  text "2. 20mil pullback on inner planes" at -3999.18,791.53 h60
  text "3. Tent all vias under BGA (Top Side only)" at -3999.18,693.11 h60
  text "4. 1.0 Oz copper on top and bottom" at -3999.18,594.68 h60
  text "5. 1.0 Oz copper on internal signal, power and ground layers" at -3999.18,492.32 h60
  text "06 FABRICATION NOTES" at 3535,-1565 h60
Mechanical 7:
  text "07" at 3535,-1665 h60
Mechanical 8:
  text "08" at 3535,-1765 h60
Mechanical 9:
  text "09" at 3535,-1865 h60
Mechanical 10:
  text "10" at 3535,-1965 h60
Mechanical 11:
  text "Design Notes" at -4000,0 h60
  text "1. Unless otherwise stated all dimensions are in mils" at -4000,-100 h60
  text "11 DESIGN INFORMATION" at 3535,-2065 h60
Mechanical 12:
  text "12 DIMENSIONS" at 3535,-2165 h60
Mechanical 13:
  lines w2: -5580,-760 -5280,-760 ; -5580,1740 -5280,1740 ; -5580,4240 -5280,4240 ; -2930,-3260 -2930,-2960 ; -2930,6440 -2930,6740 ; -255,-3260 -255,-2960 ; -255,6440 -255,6740 ; 2420,-3260 2420,-2960 ; 2420,6440 2420,6740 ; 4920,-2960 4920,-2510 5270,-2510 ; 5095,-3260 5095,-2960 ; 5095,6440 5095,6740 ; 5270,-2960 5270,-1810 6170,-1810 ; 5270,-2710 10120,-2710 ; 5270,-2410 10120,-2410 ; 5270,-2110 6170,-2110 ; 6170,-2960 6170,-1810 ; 7745,-3260 7745,-2960 ; 8170,-2710 8170,-2410 ; 9220,-2710 9220,-2410 ; 10120,-1810 6170,-1810 ; 10120,-760 10420,-760 ; 10120,4240 10420,4240 ; -5580,-3260 10420,-3260 10420,6740 -5580,6740 -5580,-3260 ; -5280,-2960 10120,-2960 10120,6440 -5280,6440 -5280,-2960
  text "1" at -4305,6540 h90
  text "2" at -1630,6540 h90
  text "3" at 1070,6540 h90
  text "4" at 3720,6540 h90
  text "5" at 6400,6540 h90
  text "D" at 10245,5490 h90
  text "D" at -5450,5465 h90
  text "C" at -5455,2965 h90
  text "B" at 10245,490 h90
  text "B" at -5455,465 h90
  text ".Drawn" at 5345,-1935 h90
  text ".Company" at 6231.22,-1944.37 h90
  text "A" at 10245,-2010 h90
  text "A" at -5450,-2085 h90
  text ".Engineer" at 5345,-2235 h90
  text "13 Height Information" at 3535,-2265 h60
  text ".Number" at 6245,-2530 h90
  text ".Print_Date" at 8280,-2530 h90
  text ".Print_Date" at 5345,-2535 h90
  text ".Revision" at 9265,-2535 h90
  text "B" at 5030,-2765 h180
  text "1:1" at 5350,-2835 h90
  text ".Pcb_File_Name_No_Path" at 6240,-2835 h90
  text "1" at 9800.91,-2880.08 h90
  text "of" at 9645,-2885 h90
  text "Sheet" at 8945,-2890 h90
  text "1" at 9331.42,-2889.92 h90
  text "Size" at 4970,-2910 h90
  text "1" at -4305,-3160 h90
  text "2" at -1630,-3160 h90
  text "3" at 1070,-3160 h90
  text "4" at 3720,-3160 h90
  text "5" at 6395,-3160 h90
  text "6" at 9070,-3160 h90
Mechanical 14:
  text "14" at 3535,-2365 h60
Mechanical 15:
  text "15 ASSEMBLY" at 3535,-2465 h60
Mechanical 16:
  lines w2: -5580,-760 -5280,-760 ; -5580,1740 -5280,1740 ; -5580,4240 -5280,4240 ; -2930,-3260 -2930,-2960 ; -2930,6440 -2930,6740 ; -255,-3260 -255,-2960 ; -255,6440 -255,6740 ; 2420,-3260 2420,-2960 ; 2420,6440 2420,6740 ; 4920,-2960 4920,-2510 5270,-2510 ; 5095,-3260 5095,-2960 ; 5095,6440 5095,6740 ; 5270,-2960 5270,-1810 6170,-1810 ; 5270,-2710 10120,-2710 ; 5270,-2410 10120,-2410 ; 5270,-2110 6170,-2110 ; 6170,-2960 6170,-1810 ; 7745,-3260 7745,-2960 ; 8170,-2710 8170,-2410 ; 9220,-2710 9220,-2410 ; 10120,-1810 6170,-1810 ; 10120,-760 10420,-760 ; 10120,4240 10420,4240 ; -5580,-3260 10420,-3260 10420,6740 -5580,6740 -5580,-3260 ; -5280,-2960 10120,-2960 10120,6440 -5280,6440 -5280,-2960
  text "1" at -4305,6540 h90
  text "2" at -1630,6540 h90
  text "3" at 1070,6540 h90
  text "4" at 3720,6540 h90
  text "5" at 6400,6540 h90
  text "D" at 10245,5490 h90
  text "D" at -5450,5465 h90
  text "C" at -5455,2965 h90
  text "B" at 10245,490 h90
  text "B" at -5455,465 h90
  text ".Drawn" at 5345,-1935 h90
  text ".Company" at 6231.22,-1944.37 h90
  text "A" at 10245,-2010 h90
  text "A" at -5450,-2085 h90
  text ".Engineer" at 5345,-2235 h90
  text ".Number" at 6245,-2530 h90
  text ".Print_Date" at 8280,-2530 h90
  text ".Print_Date" at 5345,-2535 h90
  text ".Revision" at 9265,-2535 h90
  text "16 SHEET" at 3535,-2565 h60
  text "B" at 5030,-2765 h180
  text "1:1" at 5350,-2835 h90
  text ".Pcb_File_Name_No_Path" at 6240,-2835 h90
  text "1" at 9800.91,-2880.08 h90
  text "of" at 9645,-2885 h90
  text "Sheet" at 8945,-2890 h90
  text "1" at 9331.42,-2889.92 h90
  text "Size" at 4970,-2910 h90
  text "1" at -4305,-3160 h90
  text "2" at -1630,-3160 h90
  text "3" at 1070,-3160 h90
  text "4" at 3720,-3160 h90
  text "5" at 6395,-3160 h90
  text "6" at 9070,-3160 h90
Drill Drawing:
  text "DRILL DRAWING" at 3535,-2765 h60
